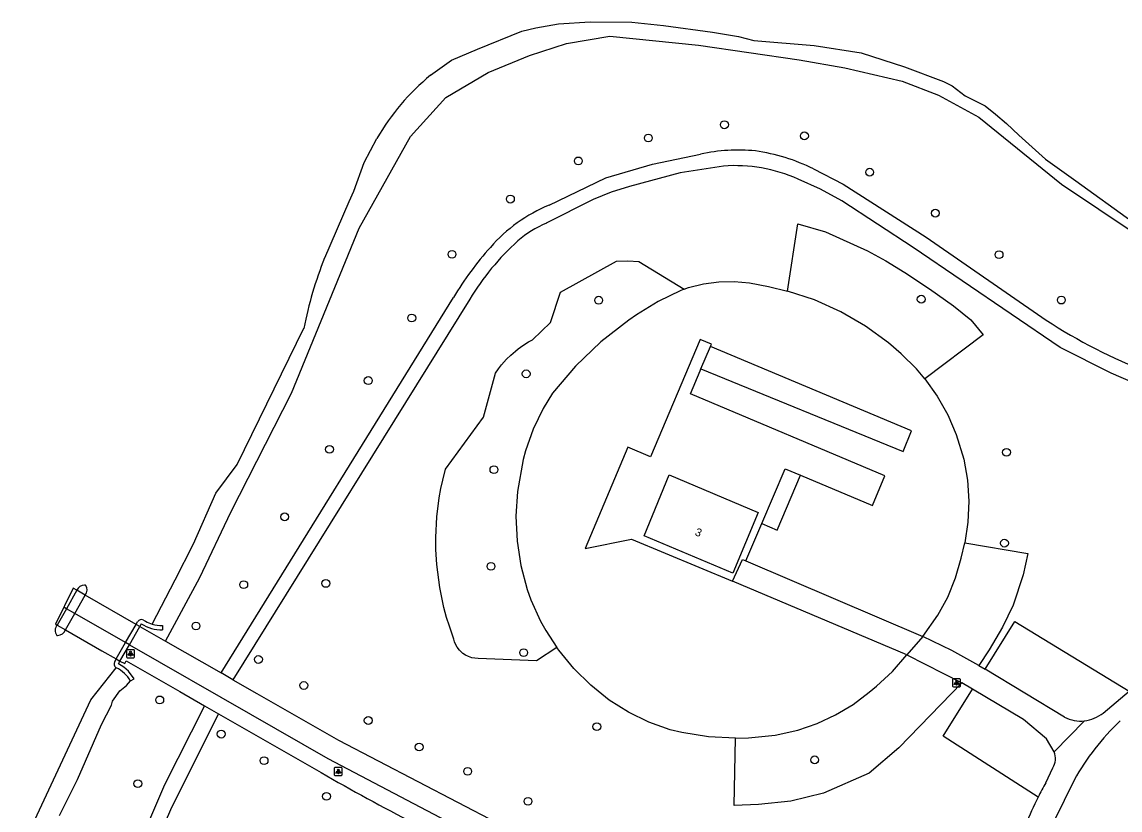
# Model space of a CAD drawing. Extents: x 162722 to 165099, y 384721 to 386283.
# Drawn here: x 162733.6 to 162870.8, y 385507.3 to 385605.8 of the extents above; entities that cross this region are included whole.
import ezdxf

# ---------------------------------------------------------------- set-up
doc = ezdxf.new("R2010")
doc.units = 0
for name, color, linetype in [('IMGEO_Boom', 7, 'Continuous'), ('IMGEO_Dek', 7, 'Continuous'), ('IMGEO_Fietspad_gesloten', 7, 'Continuous'), ('IMGEO_Fietspad_open', 7, 'Continuous'), ('IMGEO_Grasland_overig', 7, 'Continuous'), ('IMGEO_Groenvoorziening', 7, 'Continuous'), ('IMGEO_Lichtpunt', 7, 'Continuous'), ('IMGEO_Loofbos', 7, 'Continuous'), ('IMGEO_Muur', 7, 'Continuous'), ('IMGEO_Pand', 7, 'Continuous'), ('IMGEO_Pand_nummerreeks', 7, 'Continuous'), ('IMGEO_Parkeervlak_open', 7, 'Continuous'), ('IMGEO_Pijler', 7, 'Continuous'), ('IMGEO_Rijbaan_lokaal_halfverhard', 7, 'Continuous'), ('IMGEO_Voetpad_halfverhard', 7, 'Continuous'), ('IMGEO_Voetpad_open', 7, 'Continuous'), ('IMGEO_Waterloop', 7, 'Continuous')]:
    doc.layers.add(name, color=color, linetype=linetype)

msp = doc.modelspace()

# ---------------------------------------------------------------- linework, layer by layer
at = {"layer": 'IMGEO_Boom'}
for centre in [(162821.4, 385592.99), (162811.89, 385591.33), (162831.4, 385591.6), (162803.14, 385588.47), (162839.55, 385587.06), (162794.65, 385583.7), (162847.76, 385581.94), (162787.35, 385576.8), (162855.73, 385576.75), (162805.68, 385571.06), (162846, 385571.19), (162863.51, 385571.08), (162782.32, 385568.84), (162776.88, 385561.02), (162796.62, 385561.86), (162772.04, 385552.42), (162856.66, 385552.06), (162792.59, 385549.88), (162766.44, 385543.99), (162856.4, 385540.7), (162792.22, 385537.8), (162761.32, 385535.51), (162771.58, 385535.67), (162755.35, 385530.35), (162796.31, 385527.02), (162763.16, 385526.17), (162768.83, 385522.92), (162750.82, 385521.11), (162776.88, 385518.54), (162805.45, 385517.77), (162758.5, 385516.84), (162783.24, 385515.22), (162763.86, 385513.52), (162832.68, 385513.62), (162789.31, 385512.18), (162748.08, 385510.65), (162771.66, 385509.06), (162796.85, 385508.44)]:
    msp.add_circle(centre, 0.489, dxfattribs=at)
at = {"layer": 'IMGEO_Dek'}
msp.add_lwpolyline([(162737.77, 385530.57), (162737.99, 385530.45), (162739.03, 385529.86), (162743.59, 385527.25), (162745.39, 385526.23), (162745.84, 385525.94), (162747.02, 385528), (162748.33, 385530.28), (162747.88, 385530.55), (162741.51, 385534.21), (162740.44, 385534.81), (162740.01, 385535.06)], close=True, dxfattribs=at)
at = {"layer": 'IMGEO_Fietspad_gesloten'}
for points in [[(162748.33, 385530.28), (162751.56, 385528.44)], [(162747.02, 385528), (162762.16, 385519.31), (162771.84, 385513.78), (162790.77, 385503.82), (162799.32, 385500), (162799.53, 385499.91), (162826.02, 385490.12), (162837.08, 385486.71), (162843.81, 385484.68), (162853.18, 385481.95)], [(162751.56, 385528.44), (162758.49, 385524.48)], [(162759.97, 385523.64), (162762.97, 385521.93), (162773.18, 385516.08), (162792.98, 385505.75), (162800.6, 385502.36), (162806.39, 385500), (162826.86, 385492.8), (162837.65, 385489.37), (162853.35, 385484.72)]]:
    msp.add_lwpolyline(points, dxfattribs=at)
at = {"layer": 'IMGEO_Fietspad_open'}
msp.add_lwpolyline([(162747.02, 385528), (162746.56, 385528.27), (162740.2, 385531.91), (162739.15, 385532.51), (162738.83, 385532.7)], dxfattribs=at)
at = {"layer": 'IMGEO_Grasland_overig'}
for points in [[(162816.35, 385572.43), (162816.91, 385572.65), (162818.78, 385573.09), (162820.69, 385573.34), (162822.61, 385573.39), (162824.53, 385573.23), (162826.89, 385572.76), (162829.27, 385572.21)], [(162846.45, 385561.23), (162848, 385559.06), (162849.32, 385556.73), (162850.38, 385554.28), (162851.32, 385551.2), (162851.77, 385548.59), (162851.94, 385545.95), (162851.83, 385543.31), (162851.46, 385540.73)], [(162822.77, 385516.32), (162819.4, 385516.5), (162816.06, 385517.03), (162814.61, 385517.38), (162811.96, 385518.34), (162809.43, 385519.58), (162807, 385521.1), (162804.69, 385522.95), (162802.58, 385525.03), (162800.7, 385527.32), (162800.44, 385527.68)]]:
    msp.add_lwpolyline(points, dxfattribs=at)
at = {"layer": 'IMGEO_Groenvoorziening'}
for points in [[(162751.56, 385528.44), (162755.84, 385536.42), (162759.7, 385544.57), (162767.27, 385559.43), (162775.75, 385580.06), (162782.17, 385591.53), (162786.57, 385596.4), (162791.87, 385599.54), (162797.03, 385601.63), (162801.67, 385603.16), (162807.06, 385604.07), (162818.16, 385602.92), (162830.74, 385601.12), (162836.45, 385600.11), (162843.62, 385598.42), (162848.17, 385596.7), (162853.22, 385593.95), (162863.54, 385585.58), (162877.55, 385576.21)], [(162738.3, 385506.65), (162740.53, 385511.16), (162743.56, 385518.03), (162744.81, 385520.45), (162744.93, 385520.94), (162745.84, 385522.26), (162746.67, 385522.91), (162747.18, 385523.48)]]:
    msp.add_lwpolyline(points, dxfattribs=at)
at = {"layer": 'IMGEO_Lichtpunt'}
for p, q in [((162746.67, 385527.29), (162746.67, 385526.49)), ((162746.67, 385527.29), (162746.67, 385526.49)), ((162747.57, 385527.39), (162746.76, 385527.39)), ((162747.57, 385527.39), (162746.76, 385527.39)), ((162747.67, 385526.49), (162747.67, 385527.29)), ((162747.67, 385526.49), (162747.67, 385527.29)), ((162746.76, 385526.39), (162747.57, 385526.39)), ((162746.76, 385526.39), (162747.57, 385526.39)), ((162849.92, 385523.65), (162849.92, 385522.84)), ((162849.92, 385523.65), (162849.92, 385522.84)), ((162850.82, 385523.74), (162850.02, 385523.74)), ((162850.82, 385523.74), (162850.02, 385523.74)), ((162850.92, 385522.84), (162850.92, 385523.65)), ((162850.92, 385522.84), (162850.92, 385523.65)), ((162850.02, 385522.75), (162850.82, 385522.75)), ((162850.02, 385522.75), (162850.82, 385522.75)), ((162772.63, 385512.57), (162772.63, 385511.76)), ((162772.63, 385512.57), (162772.63, 385511.76)), ((162773.53, 385512.66), (162772.72, 385512.66)), ((162773.53, 385512.66), (162772.72, 385512.66)), ((162773.63, 385511.76), (162773.63, 385512.57)), ((162773.63, 385511.76), (162773.63, 385512.57)), ((162772.72, 385511.66), (162773.53, 385511.66)), ((162772.72, 385511.66), (162773.53, 385511.66))]:
    msp.add_line(p, q, dxfattribs=at)
for points in [[(162747.04, 385526.96), (162747.08, 385526.93), (162746.9, 385526.67), (162746.86, 385526.69), (162747.04, 385526.96)], [(162747.15, 385526.91), (162747.19, 385526.91), (162747.19, 385526.59), (162747.15, 385526.59), (162747.15, 385526.91)], [(162747.26, 385526.93), (162747.29, 385526.96), (162747.48, 385526.69), (162747.44, 385526.67), (162747.26, 385526.93)], [(162850.3, 385523.31), (162850.33, 385523.29), (162850.15, 385523.02), (162850.11, 385523.05), (162850.3, 385523.31)], [(162850.4, 385523.27), (162850.44, 385523.27), (162850.44, 385522.94), (162850.4, 385522.94), (162850.4, 385523.27)], [(162850.51, 385523.29), (162850.55, 385523.31), (162850.73, 385523.05), (162850.69, 385523.02), (162850.51, 385523.29)], [(162773, 385512.23), (162773.04, 385512.2), (162772.86, 385511.94), (162772.82, 385511.97), (162773, 385512.23)], [(162773.11, 385512.18), (162773.15, 385512.18), (162773.15, 385511.86), (162773.11, 385511.86), (162773.11, 385512.18)], [(162773.22, 385512.2), (162773.25, 385512.23), (162773.44, 385511.97), (162773.4, 385511.94), (162773.22, 385512.2)]]:
    msp.add_lwpolyline(points, dxfattribs=at)
for centre in [(162747.17, 385527.09), (162850.42, 385523.45), (162773.13, 385512.36)]:
    msp.add_circle(centre, 0.0994, dxfattribs=at)
for centre, start, end in [((162746.76, 385527.29), 90, 180), ((162746.76, 385527.29), 90, 180), ((162747.57, 385527.29), 0, 90), ((162747.57, 385527.29), 0, 90), ((162746.76, 385526.49), 180, 270), ((162746.76, 385526.49), 180, 270), ((162747.57, 385526.49), 270, 0), ((162747.57, 385526.49), 270, 360), ((162850.02, 385523.65), 90, 180), ((162850.02, 385523.65), 90, 180), ((162850.82, 385523.65), 0, 90), ((162850.82, 385523.65), 0, 90), ((162850.02, 385522.84), 180, 270), ((162850.02, 385522.84), 180, 270), ((162850.82, 385522.84), 270, 0), ((162850.82, 385522.84), 270, 360), ((162772.72, 385512.57), 90, 180), ((162772.72, 385512.57), 90, 180), ((162773.53, 385512.57), 0, 90), ((162773.53, 385512.57), 0, 90), ((162772.72, 385511.76), 180, 270), ((162772.72, 385511.76), 180, 270), ((162773.53, 385511.76), 270, 0), ((162773.53, 385511.76), 270, 360)]:
    msp.add_arc(centre, 0.0946, start, end, dxfattribs=at)
at = {"layer": 'IMGEO_Loofbos'}
for points in [[(162829.27, 385572.21), (162830.56, 385580.62), (162834.04, 385579.62), (162839.3, 385577.23), (162841.58, 385575.97), (162843.94, 385574.51), (162847.04, 385572.47), (162850.05, 385570.35), (162852.21, 385568.6), (162853.74, 385566.73), (162846.45, 385561.23)], [(162800.44, 385527.68), (162797.92, 385525.99), (162790.6, 385526.29), (162790.2, 385526.31), (162789.84, 385526.38), (162789.41, 385526.52), (162789.03, 385526.71), (162788.72, 385526.92), (162788.27, 385527.34), (162788, 385527.71), (162787.8, 385528.08), (162787.68, 385528.35), (162787.58, 385528.71), (162787.02, 385530.31), (162786.68, 385531.41), (162786.33, 385532.68), (162785.82, 385535.16), (162785.45, 385538.05), (162785.34, 385539.92), (162785.33, 385541.42), (162785.47, 385544.01), (162785.76, 385546.35), (162785.97, 385547.52), (162786.19, 385548.57), (162786.54, 385549.96), (162791.28, 385556.44), (162792.79, 385561.95), (162793.18, 385562.5), (162793.55, 385562.99), (162794.18, 385563.7), (162794.71, 385564.21), (162795.28, 385564.71), (162795.62, 385564.98), (162796.22, 385565.41), (162796.93, 385565.85), (162797.4, 385566.11), (162799.65, 385568.29), (162800.93, 385572.06), (162807.91, 385575.94), (162809.31, 385576), (162810.71, 385575.89), (162816.35, 385572.43)], [(162816.35, 385572.43), (162815.97, 385572.27), (162813.12, 385570.89), (162810.42, 385569.22), (162809.46, 385568.57), (162805.96, 385565.87), (162802.77, 385562.82), (162799.92, 385559.46), (162798.76, 385557.53), (162797.51, 385554.94), (162796.54, 385552.24), (162796.24, 385551.14), (162795.52, 385547.16), (162795.34, 385544.07), (162795.48, 385540.97), (162795.95, 385537.9), (162796.73, 385534.9), (162797.2, 385533.63), (162798.43, 385530.95), (162799.08, 385529.8), (162800.44, 385527.68)], [(162846.45, 385561.23), (162845.39, 385562.48), (162843.49, 385564.37), (162841.92, 385565.72), (162839.03, 385567.83), (162835.94, 385569.63), (162832.67, 385571.09), (162829.27, 385572.21)], [(162846.22, 385529.03), (162848.09, 385531.69), (162849.31, 385533.96), (162850.28, 385536.35), (162851, 385538.82), (162851.46, 385540.73)], [(162851.46, 385540.73), (162859.33, 385539.42), (162858.73, 385536.73), (162857.51, 385532.97), (162856.14, 385530.2), (162854.51, 385527.35), (162853.2, 385525.43)], [(162822.77, 385516.32), (162824.39, 385516.36), (162827.74, 385516.7), (162830.57, 385517.33), (162832.98, 385518.16), (162835.29, 385519.24), (162837.48, 385520.55), (162839.51, 385522.09), (162840.42, 385522.82), (162842.42, 385524.68), (162844.21, 385526.74)], [(162851.08, 385523.24), (162843.18, 385515.14), (162839.49, 385511.96), (162833.77, 385509.46), (162829.71, 385508.45), (162825.64, 385508.06), (162822.62, 385507.91), (162822.77, 385516.32)]]:
    msp.add_lwpolyline(points, dxfattribs=at)
at = {"layer": 'IMGEO_Muur'}
for points in [[(162745.21, 385525.89), (162745.39, 385526.23), (162746.56, 385528.27), (162747.88, 385530.55), (162748.06, 385530.9)], [(162747.02, 385528), (162748.33, 385530.28)], [(162748.51, 385530.6), (162748.33, 385530.28)], [(162748.79, 385531.09), (162749.03, 385530.94)], [(162751.16, 385530.4), (162751.17, 385529.88)], [(162745.84, 385525.94), (162747.02, 385528)], [(162747.18, 385523.48), (162747.64, 385523.73), (162746.93, 385524.7), (162746.32, 385525.22), (162745.68, 385525.6), (162745.84, 385525.94)]]:
    msp.add_lwpolyline(points, dxfattribs=at)
for centre, radius, start, end in [((162748.53, 385530.6), 0.554, 61.9027, 146.7649), ((162751.05, 385534.66), 4.78, 237.9543, 271.4406), ((162751.14, 385534.69), 4.3, 240.6258, 252.9607), ((162751.13, 385534.73), 4.33, 253.2411, 270.3984), ((162745.65, 385525.6), 0.533, 146.3529, 240.2209), ((162743.39, 385521.18), 4.43, 31.1786, 63.1398)]:
    msp.add_arc(centre, radius, start, end, dxfattribs=at)
at = {"layer": 'IMGEO_Pand'}
msp.add_lwpolyline([(162825.61, 385544.52), (162822.45, 385536.96), (162811.36, 385541.63), (162814.49, 385549.22), (162825.61, 385544.52)], dxfattribs=at)
at = {"layer": 'IMGEO_Parkeervlak_open'}
for points in [[(162854, 385524.95), (162857.7, 385530.92), (162871.97, 385522.21)], [(162860.62, 385508.97), (162848.73, 385516.59), (162852.4, 385522.45)]]:
    msp.add_lwpolyline(points, dxfattribs=at)
at = {"layer": 'IMGEO_Pijler'}
for points in [[(162741.55, 385535.46), (162741.48, 385535.47), (162741.43, 385535.47)], [(162740.44, 385534.81), (162739.15, 385532.51), (162737.99, 385530.45)], [(162739.03, 385529.86), (162740.2, 385531.91), (162741.51, 385534.21)], [(162737.95, 385529.18), (162738.06, 385529.17)]]:
    msp.add_lwpolyline(points, dxfattribs=at)
for centre, radius, start, end in [((162741.47, 385534.33), 1.14, 92.0515, 154.6851), ((162740.7, 385534.86), 1.05, 321.0369, 35.0477), ((162738.82, 385529.79), 1.07, 141.6022, 215.0707), ((162738.03, 385530.24), 1.07, 271.2754, 338.9929)]:
    msp.add_arc(centre, radius, start, end, dxfattribs=at)
at = {"layer": 'IMGEO_Rijbaan_lokaal_halfverhard'}
for points in [[(162799.49, 385582.96), (162806.56, 385586.34), (162812.42, 385588.05), (162818.42, 385589.31)], [(162821.28, 385587.82), (162815.86, 385586.97), (162809.55, 385585.29), (162807.24, 385584.57), (162805, 385583.66), (162799.14, 385580.69)], [(162832.52, 385587.47), (162836.26, 385585.55), (162846.63, 385578.93), (162861.6, 385568.59)], [(162909.77, 385549.09), (162895.97, 385552.12), (162889.16, 385554.09), (162880.22, 385557.41), (162869.74, 385561.96), (162863.35, 385565.14), (162844.98, 385577.67), (162836.08, 385583.47), (162833.39, 385584.93), (162830.6, 385586.2)], [(162758.49, 385524.48), (162787.55, 385571.41)], [(162789.58, 385571.19), (162759.97, 385523.64)], [(162822.39, 385535.95), (162823.68, 385538.65), (162824.06, 385538.48)], [(162824.06, 385538.48), (162846.22, 385529.03)], [(162844.21, 385526.74), (162822.39, 385535.95)], [(162846.22, 385529.03), (162844.21, 385526.74)], [(162853.2, 385525.43), (162849.84, 385527.29), (162846.22, 385529.03)], [(162844.21, 385526.74), (162851.08, 385523.24)], [(162759.97, 385523.64), (162758.49, 385524.48)], [(162853.2, 385525.43), (162854, 385524.95)], [(162863.91, 385518.95), (162854, 385524.95)], [(162852.4, 385522.45), (162851.08, 385523.24)], [(162862.61, 385514.61), (162861.66, 385516.23), (162858.78, 385518.67), (162852.4, 385522.45)], [(162868.73, 385519.47), (162871.97, 385522.21)], [(162862.61, 385514.61), (162866.4, 385518.5)], [(162861.56, 385510.76), (162862.46, 385512.62)], [(162865.11, 385511.1), (162861.37, 385503.47), (162860.14, 385500), (162855.98, 385483.95)]]:
    msp.add_lwpolyline(points, dxfattribs=at)
for centre, radius, start, end in [((162823.07, 385569), 20.83, 83.9282, 102.889), ((162822.1, 385566.62), 23.31, 63.4489, 82.1667), ((162822.71, 385568.38), 19.5, 66.1027, 94.1984), ((162807.04, 385564.75), 19.71, 112.5136, 139.0693), ((162803.73, 385569.41), 12.18, 112.1271, 131.9734), ((162816.82, 385554.81), 31.79, 131.9213, 148.9977), ((162820.83, 385551.76), 38.65, 137.9152, 149.4406), ((162899.95, 385627.53), 70.32, 236.9511, 248.6414), ((162865.92, 385522.91), 4.44, 243.1447, 276.2618), ((162865.92, 385522.91), 4.44, 276.1897, 309.2732), ((162893.22, 385495.19), 32.3, 133.834, 150.4912), ((162860.46, 385513.77), 2.31, 330.1965, 21.4071), ((162909.2, 385484.54), 54.38, 151.1783, 153.3073), ((162909.57, 385484.3), 54.81, 153.2576, 161.1851)]:
    msp.add_arc(centre, radius, start, end, dxfattribs=at)
at = {"layer": 'IMGEO_Voetpad_halfverhard'}
msp.add_lwpolyline([(162756.42, 385520.38), (162751.41, 385510.49), (162746.91, 385500), (162743.14, 385491.2), (162740.5, 385483.47), (162738.35, 385472.83), (162737.47, 385466.79), (162736.19, 385456.16), (162735.2, 385441.61), (162735.31, 385438.72), (162736.61, 385424.61), (162738.57, 385412.43), (162740.34, 385412.61), (162738.14, 385430.01), (162737.76, 385436.04), (162737.51, 385446.31), (162738.66, 385462.57), (162740.37, 385472.18), (162743.43, 385483.85), (162745.98, 385491.97), (162747.67, 385496.13), (162748.99, 385500), (162752.22, 385507.4), (162758.18, 385519.37)], dxfattribs=at)
at = {"layer": 'IMGEO_Voetpad_open'}
for points in [[(162819.65, 385565.29), (162819.77, 385565.57), (162818.35, 385566.17), (162812.17, 385551.49), (162809.33, 385552.68), (162804, 385540.03), (162809.77, 385541.18), (162822.39, 385535.95)], [(162818.47, 385562.49), (162819.65, 385565.29)], [(162818.47, 385562.49), (162843.73, 385552.16), (162844.79, 385554.75), (162819.65, 385565.29)], [(162830.9, 385549.2), (162839.91, 385545.41), (162841.47, 385549.12), (162817.15, 385559.36), (162818.36, 385562.24), (162818.47, 385562.49)], [(162826.06, 385543.17), (162828.98, 385550.01), (162830.9, 385549.2)], [(162826.06, 385543.17), (162828.01, 385542.34), (162830.9, 385549.2)], [(162824.06, 385538.48), (162826.06, 385543.17)], [(162745.84, 385525.94), (162746.46, 385525.65), (162746.64, 385526), (162753.35, 385522.16), (162756.42, 385520.38)], [(162756.42, 385520.38), (162758.18, 385519.37)], [(162758.18, 385519.37), (162770.99, 385512.04)]]:
    msp.add_lwpolyline(points, dxfattribs=at)
msp.add_arc((162895.06, 385725.54), 246.93, 239.8382, 245.9728, dxfattribs=at)
at = {"layer": 'IMGEO_Waterloop'}
for points in [[(162784.68, 385599.17), (162787.29, 385601.05), (162790.53, 385602.42), (162796.09, 385604.68), (162797.83, 385605.09), (162800.66, 385605.59), (162804.62, 385605.84), (162809.83, 385605.8), (162813.78, 385605.4), (162819.91, 385604.58), (162823.16, 385604.03), (162825.08, 385603.5), (162832.62, 385602.9), (162838.5, 385601.99), (162843.9, 385600.24), (162848.78, 385598.41), (162849.88, 385597.85), (162851.5, 385596.59), (162854, 385595.37), (162855.29, 385594.3), (162856.64, 385593.14), (162858.18, 385591.71), (162861.54, 385588.69), (162865.33, 385585.98), (162872.35, 385580.9)], [(162771.44, 385576.34), (162774.49, 385583.39), (162775.06, 385584.7), (162776.38, 385588.28), (162777.97, 385591.27)], [(162749.88, 385530.58), (162752.74, 385536.13), (162755.05, 385540.61), (162757.83, 385546.93), (162760.49, 385550.54), (162768.85, 385567.55)], [(162733.6, 385502.64), (162734, 385503.52), (162734.34, 385504.25), (162742.2, 385521.14), (162745.39, 385525.14)]]:
    msp.add_lwpolyline(points, dxfattribs=at)
for centre, radius, start, end in [((162802.65, 385577.13), 28.44, 129.1869, 150.1931), ((162814.34, 385558.95), 46.3, 157.9395, 169.2969)]:
    msp.add_arc(centre, radius, start, end, dxfattribs=at)

# ---------------------------------------------------------------- texts
at = {"layer": 'IMGEO_Pand_nummerreeks'}
msp.add_text('3', height=1, rotation=337.167, dxfattribs=at).set_placement((162817.63, 385541.73))

doc.saveas('drawing.dxf')
